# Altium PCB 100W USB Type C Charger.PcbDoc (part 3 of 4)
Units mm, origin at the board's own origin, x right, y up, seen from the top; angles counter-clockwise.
Board outline 79.45 x 55.68 mm, 4 copper layers (Top Layer, Signal Layer 1, Signal Layer 2, Bottom Layer), stack 1.565 mm thick; 161 components, 84 nets, 462 pads, 2175 vias.
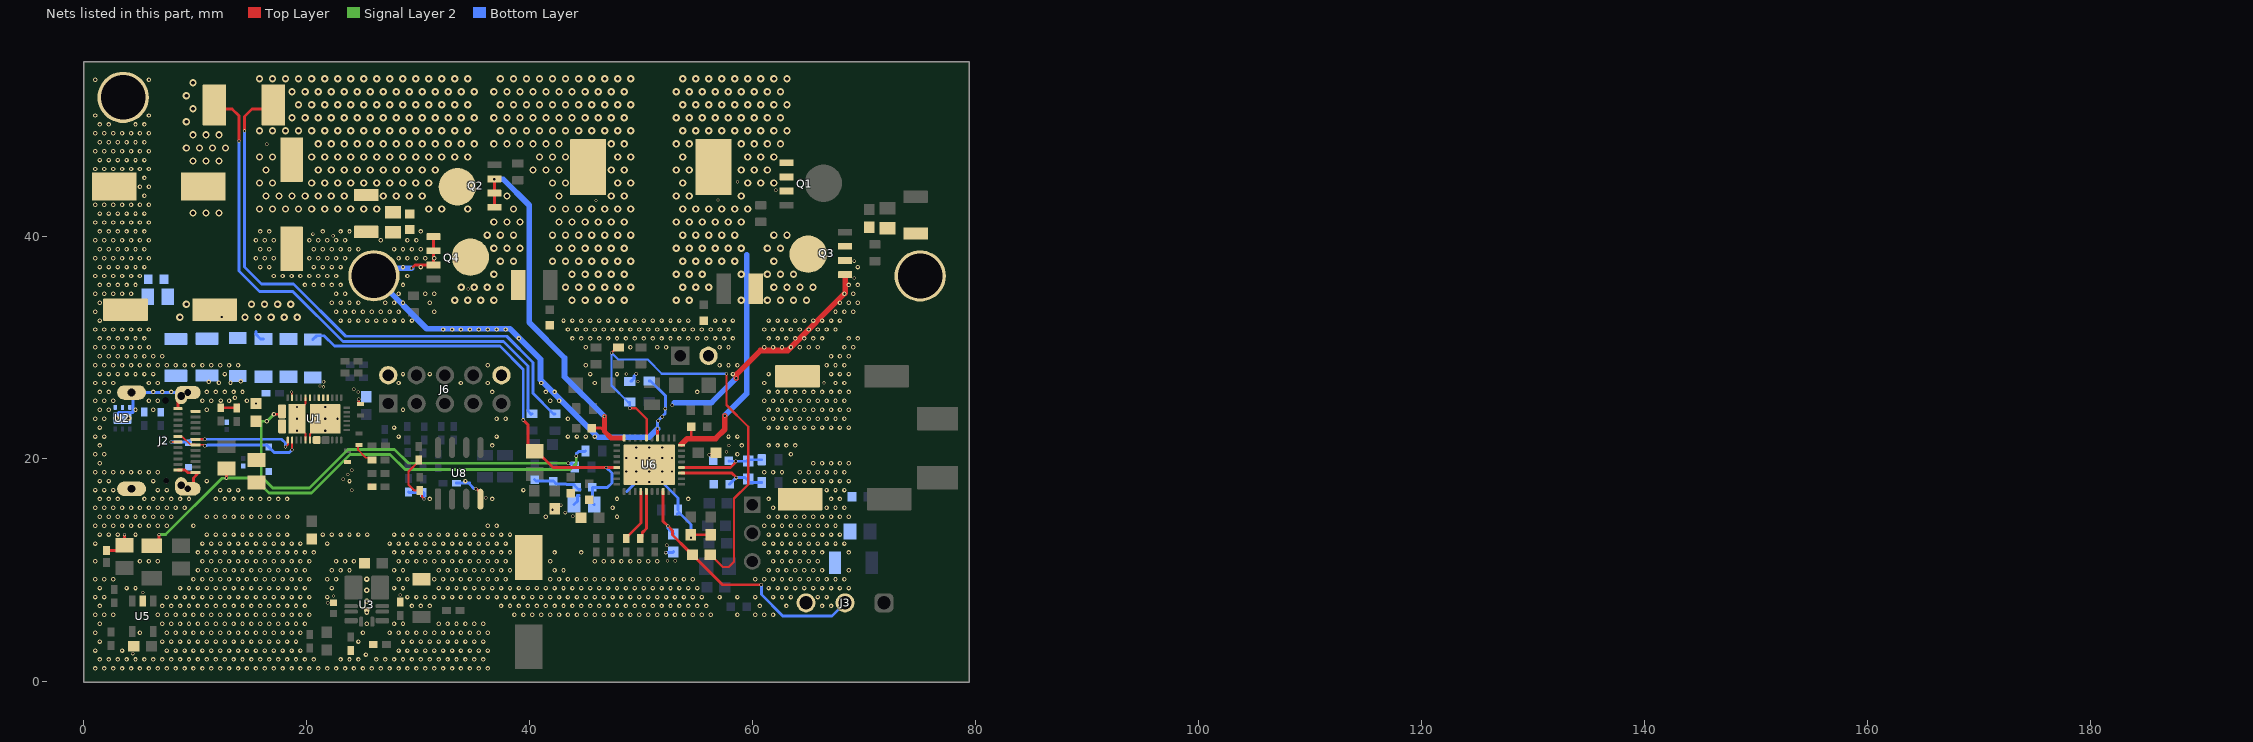
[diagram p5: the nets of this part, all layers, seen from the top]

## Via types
v1: diameter 0.4, hole 0.2, Top Layer to Bottom Layer, 1357 vias
v2: diameter 0.66, hole 0.33, Top Layer to Bottom Layer, 627 vias
v3: diameter 0.3, hole 0.2, Top Layer to Bottom Layer, tented both sides, 152 vias
v4: diameter 0.5, hole 0.2, Top Layer to Bottom Layer, 18 vias
v5: diameter 0.5, hole 0.2, Top Layer to Bottom Layer, tented both sides, 16 vias
v6: diameter 0.4, hole 0.2, Top Layer to Bottom Layer, tented both sides, 3 vias
v7: diameter 0.35, hole 0.2, Top Layer to Bottom Layer, tented both sides, 2 vias

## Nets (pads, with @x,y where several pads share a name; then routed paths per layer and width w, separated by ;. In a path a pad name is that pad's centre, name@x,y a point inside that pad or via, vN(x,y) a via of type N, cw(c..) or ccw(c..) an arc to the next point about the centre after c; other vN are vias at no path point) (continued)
PGND: C1.2 C2.2 C3.2 C4.2 C5.2 C6.2 C7.1 C8.1 C9.1 C10.2 C11.2 C12.2 C13.2 C14.2 C15.2 C16.2 C17.2 C18.2 C20.2 C21.2 C22.2 C24.2 C25.2 C29.1 C30.2 C31.2 C32.2 C33.2 C35.2 C36.2 C37.2 C40.2 C41.2 C42.2 C43.1 C44.1 C47.2 C48.2 C49.1 C51.1 C53.1 C54.2 C56.2 C57.2 C58.2 C59.1 C60.2 C61.2 C62.2 C63.2 C64.2 C67.1 C68.2 C69.2 C70.2 D1.1 D2.1 D3.2 J2.A1 J2.A12 J2.B1 J2.B12 J2.S1 J2.S2 J2.S3 J2.S4 J3.3 J4.2 J6.2 J6.10 pad.2 Q3.1 Q3.2 Q3.3 Q4.1 Q4.2 Q4.3 R2.1 R17.1 R18.1 R22.1 R23.1 R24.1 R30.1 R32.2 R52.1 R54.1 R58.2 R60.1 R61.1 R62.1 R63.1 R74.1 U1.10 U1.11 U1.12 U1.14 U1.18 U1.31 U1.39 U2.1 U2.2 U2.3 U2.7@3.474,23.658 U3.10 U5.2 U6.22 U6.37 U8.4 | length 119.3
  Top Layer w0.152: v3(18.644,26.014) 18.67,25.988 18.67,25.523 U1.18@18.694,25.499 ; U1.31@20.294,21.699 20.294,22.269 21.624,23.599 v5(21.659,23.599) ; C8.1@24.584,21.265 C8.1@24.698,21.265 24.6,21.167 24.6,20.814 25.314,20.1 25.556,20.1 R2.1@25.744,19.912
  Top Layer w0.2: v3(24.674,25.362) 24.674,25.011 C9.1@24.755,24.93 ; C15.2@29.962,20.006 C15.2@29.962,20.106 ; C15.2@30.064,19.904 30.064,19.804 29.139,18.879 29.139,17.697 29.665,17.171 30.153,17.171 R22.1@30.153,17.159 30.353,16.959 30.353,16.612 30.523,16.442 v3(30.523,16.415) ; v3(35.172,17.322) 35.191,17.303 35.25,17.303 35.587,16.966 U8.4@35.587,16.395
  Top Layer w0.254: D3.2@2.04,11.799 3.19,11.799 C24.2@3.656,12.265 v3(3.656,13.213) ; J2.B1@8.443,19.017 9.092,19.017 9.342,18.767 J2.A12@10.043,18.767 ; J2.B12@8.443,24.517 8.443,25.356 8.724,25.637 J2.S1@8.743,25.637 ; J2.S2@9.343,17.322 9.405,17.322 9.842,17.759 9.842,18.303 10.163,18.625 ; J2.A1@9.728,24.267 J2.A1@10.043,24.267 ; C5.2@12.285,24.595 13.698,24.595 C6.2@13.733,24.56 13.733,24.66 C6.2@13.906,24.833 ; R30.1@25.671,17.677 R30.1@25.844,17.504 ; v3(29.4,37.103) 29.413,37.103 29.718,37.408 Q4.3@31.377,37.408 Q4.2@31.377,38.678 Q4.1@31.377,39.948 Q4.1@31.046,39.948 ; U6.22@51.481,21.883 v3(51.481,22.706) ; R60.1@54.453,13.196 R54.1@56.237,13.196 ; v3(56.123,20.387) 56.582,20.387 R61.1@56.736,20.541
  Top Layer w0.508: v3(58.548,27.247) 58.548,27.58 60.705,29.737 63.154,29.737 68.308,34.891 Q3.1@68.308,36.539
  Top Layer w1: J2.S1@8.793,25.962 J2.S1@9.343,25.962 J2.S1@9.948,25.962
  Bottom Layer w0.254: 3.131,24.17 3.118,24.183 4.418,24.183 4.418,25.838 J2.S3@4.293,25.962 J2.S1@9.343,25.962 ; R23.1@29.139,17.047 29.204,16.982 R24.1@30.453,16.982 30.514,16.921 30.514,16.424 v3(30.523,16.415) ; R74.1@33.424,17.832 34.627,17.832 34.595,17.8 34.595,17.754 35.018,17.331 35.163,17.331 v3(35.172,17.322) ; C30.2@40.452,18.157 40.596,18.013 C31.2@42.14,18.013 42.394,17.759 43.266,17.759 43.313,17.711 43.321,17.711 43.336,17.697 43.956,17.697 C43.1@44.21,17.443 44.4,17.253 C43.1@44.544,17.253 ; C41.2@43.993,15.907 44.296,16.209 44.296,16.745 44.427,16.745 44.432,16.75 ; 48.721,17.083 v4(49.571,17.933) ; C47.2@49.089,26.974 49.118,26.974 49.372,27.228 49.372,27.438 49.571,27.637 v3(49.571,27.649) ; C42.2@50.731,26.992 50.856,26.992 52.179,25.669 v3(52.179,24.517) 52.17,24.509 52.17,24.082 51.892,23.804 v3(51.892,23.791) v3(51.535,23.434) 51.481,23.381 v3@51.481,22.718 ; v4(51.891,17.933) 53.31,16.514 R58.2@53.31,15.423 ; v3(52.214,11.601) 52.841,11.601 R62.1@52.905,11.665 R62.1@52.905,11.69 ; R58.2@53.253,15.05 53.401,15.198 53.41,15.198 54.491,14.117 v3(54.491,12.934)
  Bottom Layer w0.5: 46.14,21.95 46.149,21.959 48.629,21.959 48.638,21.95 50.726,21.95
  Bottom Layer w0.508: v3(29.4,37.103) 27.719,37.103 26.537,35.921 30.77,31.688 38.237,31.688 40.979,28.946 40.979,27.111 46.14,21.95 ; 50.726,21.95 v3(51.481,22.706) ; 52.979,25.053 56.326,25.053 58.52,27.247 v3(58.548,27.247)
  other v1: 1.043,1.215 1.843,1.215 2.643,1.215 3.443,1.215 4.243,1.215 5.043,1.215 5.843,1.215 6.643,1.215 7.443,1.215 8.243,1.215 9.043,1.215 9.843,1.215 10.643,1.215 11.443,1.215 12.243,1.215 13.043,1.215 13.843,1.215 14.643,1.215 15.443,1.215 16.243,1.215 17.043,1.215 17.843,1.215 18.643,1.215 19.443,1.215 20.243,1.215 21.043,1.215 21.843,1.215 22.643,1.215 23.443,1.215 24.243,1.215 25.043,1.215 25.843,1.215 26.643,1.215 27.443,1.215 28.243,1.215 29.043,1.215 29.843,1.215 30.643,1.215 31.443,1.215 32.243,1.215 33.043,1.215 33.843,1.215 34.643,1.215 35.443,1.215 36.243,1.215 1.443,2.015 2.243,2.015 3.043,2.015 3.843,2.015 4.643,2.015 5.443,2.015 6.243,2.015 7.043,2.015 7.843,2.015 8.643,2.015 9.443,2.015 10.243,2.015 11.043,2.015 11.843,2.015 12.643,2.015 13.443,2.015 14.243,2.015 15.043,2.015 15.843,2.015 16.643,2.015 17.443,2.015 18.243,2.015 19.043,2.015 19.843,2.015 20.643,2.015 23.043,2.015 23.843,2.015 24.643,2.015 26.243,2.015 27.043,2.015 27.843,2.015 28.643,2.015 29.443,2.015 30.243,2.015 31.043,2.015 31.843,2.015 32.643,2.015 33.443,2.015 34.243,2.015 35.043,2.015 35.843,2.015 1.043,2.815 3.443,2.815 7.443,2.815 8.243,2.815 9.043,2.815 9.843,2.815 10.643,2.815 11.443,2.815 12.243,2.815 13.043,2.815 13.843,2.815 14.643,2.815 15.443,2.815 16.243,2.815 17.043,2.815 17.843,2.815 18.643,2.815 19.443,2.815 28.243,2.815 29.043,2.815 29.843,2.815 30.643,2.815 31.443,2.815 32.243,2.815 33.043,2.815 33.843,2.815 34.643,2.815 35.443,2.815 36.243,2.815 1.443,3.615 7.043,3.615 7.843,3.615 8.643,3.615 9.443,3.615 10.243,3.615 11.043,3.615 11.843,3.615 12.643,3.615 13.443,3.615 14.243,3.615 15.043,3.615 15.843,3.615 16.643,3.615 17.443,3.615 18.243,3.615 19.043,3.615 24.643,3.615 28.643,3.615 29.443,3.615 30.243,3.615 31.043,3.615 31.843,3.615 32.643,3.615 33.443,3.615 34.243,3.615 35.043,3.615 35.843,3.615 1.043,4.415 5.043,4.415 7.443,4.415 8.243,4.415 9.043,4.415 9.843,4.415 10.643,4.415 11.443,4.415 12.243,4.415 13.043,4.415 13.843,4.415 14.643,4.415 15.443,4.415 16.243,4.415 17.043,4.415 17.843,4.415 18.643,4.415 19.443,4.415 25.043,4.415 27.443,4.415 28.243,4.415 29.043,4.415 29.843,4.415 30.643,4.415 31.443,4.415 32.243,4.415 33.043,4.415 33.843,4.415 34.643,4.415 35.443,4.415 36.243,4.415 1.443,5.215 7.043,5.215 7.843,5.215 8.643,5.215 9.443,5.215 10.243,5.215 11.043,5.215 11.843,5.215 12.643,5.215 13.443,5.215 14.243,5.215 15.043,5.215 15.843,5.215 16.643,5.215 17.443,5.215 18.243,5.215 19.043,5.215 19.843,5.215 27.843,5.215 28.643,5.215 31.843,5.215 32.643,5.215 33.443,5.215 34.243,5.215 35.043,5.215 35.843,5.215 1.043,6.015 1.843,6.015 2.643,6.015 6.643,6.015 7.443,6.015 8.243,6.015 9.043,6.015 9.843,6.015 10.643,6.015 11.443,6.015 12.243,6.015 13.043,6.015 13.843,6.015 14.643,6.015 15.443,6.015 16.243,6.015 17.043,6.015 17.843,6.015 18.643,6.015 19.443,6.015 20.243,6.015 38.643,6.015 39.443,6.015 40.243,6.015 41.043,6.015 41.843,6.015 42.643,6.015 43.443,6.015 44.243,6.015 45.043,6.015 45.843,6.015 46.643,6.015 47.443,6.015 48.243,6.015 49.043,6.015 49.843,6.015 50.643,6.015 51.443,6.015 52.243,6.015 53.043,6.015 53.843,6.015 54.643,6.015 55.443,6.015 56.243,6.015 58.643,6.015 60.243,6.015 61.043,6.015 61.843,6.015 1.443,6.815 7.043,6.815 7.843,6.815 8.643,6.815 9.443,6.815 10.243,6.815 11.043,6.815 11.843,6.815 12.643,6.815 13.443,6.815 14.243,6.815 15.043,6.815 15.843,6.815 16.643,6.815 17.443,6.815 18.243,6.815 19.043,6.815 19.843,6.815 29.443,6.815 30.243,6.815 31.043,6.815 37.443,6.815 38.243,6.815 39.043,6.815 39.843,6.815 40.643,6.815 41.443,6.815 42.243,6.815 43.043,6.815 43.843,6.815 44.643,6.815 45.443,6.815 46.243,6.815 47.043,6.815 47.843,6.815 48.643,6.815 49.443,6.815 50.243,6.815 51.043,6.815 51.843,6.815 52.643,6.815 53.443,6.815 54.243,6.815 55.043,6.815 55.843,6.815 60.643,6.815 63.043,6.815 66.243,6.815 67.043,6.815 1.043,7.615 1.843,7.615 7.443,7.615 8.243,7.615 9.043,7.615 9.843,7.615 10.643,7.615 11.443,7.615 12.243,7.615 13.043,7.615 13.843,7.615 14.643,7.615 15.443,7.615 16.243,7.615 17.043,7.615 17.843,7.615 18.643,7.615 19.443,7.615 20.243,7.615 21.843,7.615 29.043,7.615 29.843,7.615 30.643,7.615 31.443,7.615 32.243,7.615 33.043,7.615 33.843,7.615 34.643,7.615 35.443,7.615 36.243,7.615 37.043,7.615 37.843,7.615 38.643,7.615 39.443,7.615 40.243,7.615 41.043,7.615 41.843,7.615 42.643,7.615 43.443,7.615 44.243,7.615 45.043,7.615 45.843,7.615 46.643,7.615 47.443,7.615 48.243,7.615 49.043,7.615 49.843,7.615 50.643,7.615 51.443,7.615 52.243,7.615 53.043,7.615 53.843,7.615 54.643,7.615 55.443,7.615 57.043,7.615 58.643,7.615 60.243,7.615 61.843,7.615 62.643,7.615 63.443,7.615 65.843,7.615 66.643,7.615 1.443,8.415 3.843,8.415 4.643,8.415 8.643,8.415 9.443,8.415 10.243,8.415 11.043,8.415 11.843,8.415 12.643,8.415 13.443,8.415 14.243,8.415 15.043,8.415 15.843,8.415 16.643,8.415 17.443,8.415 18.243,8.415 19.043,8.415 19.843,8.415 22.243,8.415 27.843,8.415 28.643,8.415 31.843,8.415 32.643,8.415 33.443,8.415 34.243,8.415 35.043,8.415 35.843,8.415 36.643,8.415 37.443,8.415 38.243,8.415 39.043,8.415 39.843,8.415 40.643,8.415 41.443,8.415 42.243,8.415 43.043,8.415 43.843,8.415 44.643,8.415 45.443,8.415 46.243,8.415 47.043,8.415 47.843,8.415 48.643,8.415 49.443,8.415 50.243,8.415 51.043,8.415 51.843,8.415 52.643,8.415 53.443,8.415 54.243,8.415 55.043,8.415 61.443,8.415 62.243,8.415 63.043,8.415 63.843,8.415 64.643,8.415 65.443,8.415 66.243,8.415 67.043,8.415 67.843,8.415 68.643,8.415 1.043,9.215 1.843,9.215 2.643,9.215 9.843,9.215 10.643,9.215 11.443,9.215 12.243,9.215 13.043,9.215 13.843,9.215 14.643,9.215 15.443,9.215 16.243,9.215 17.043,9.215 17.843,9.215 18.643,9.215 19.443,9.215 20.243,9.215 21.843,9.215 22.643,9.215 28.243,9.215 29.043,9.215 31.443,9.215 32.243,9.215 33.043,9.215 33.843,9.215 34.643,9.215 35.443,9.215 36.243,9.215 37.043,9.215 37.843,9.215 41.843,9.215 42.643,9.215 43.443,9.215 44.243,9.215 45.043,9.215 45.843,9.215 46.643,9.215 47.443,9.215 48.243,9.215 49.043,9.215 49.843,9.215 50.643,9.215 51.443,9.215 52.243,9.215 53.043,9.215 53.843,9.215 54.643,9.215 60.243,9.215 61.043,9.215 61.843,9.215 62.643,9.215 63.443,9.215 64.243,9.215 65.043,9.215 65.843,9.215 66.643,9.215 67.443,9.215 68.243,9.215 10.243,10.015 11.043,10.015 11.843,10.015 12.643,10.015 13.443,10.015 14.243,10.015 15.043,10.015 15.843,10.015 16.643,10.015 17.443,10.015 18.243,10.015 19.043,10.015 19.843,10.015 22.243,10.015 23.043,10.015 23.843,10.015 27.843,10.015 28.643,10.015 31.843,10.015 32.643,10.015 33.443,10.015 34.243,10.015 35.043,10.015 35.843,10.015 36.643,10.015 37.443,10.015 38.243,10.015 42.243,10.015 43.043,10.015 61.443,10.015 62.243,10.015 63.043,10.015 63.843,10.015 64.643,10.015 65.443,10.015 66.243,10.015 68.643,10.015 1.043,10.815 5.043,10.815 5.843,10.815 6.643,10.815 10.643,10.815 11.443,10.815 12.243,10.815 13.043,10.815 13.843,10.815 14.643,10.815 15.443,10.815 16.243,10.815 17.043,10.815 17.843,10.815 18.643,10.815 19.443,10.815 20.243,10.815 22.643,10.815 23.443,10.815 24.243,10.815 28.243,10.815 29.043,10.815 29.843,10.815 30.643,10.815 31.443,10.815 32.243,10.815 33.043,10.815 33.843,10.815 34.643,10.815 35.443,10.815 36.243,10.815 37.043,10.815 37.843,10.815 41.843,10.815 45.843,10.815 46.643,10.815 47.443,10.815 48.243,10.815 49.043,10.815 49.843,10.815 50.643,10.815 51.443,10.815 61.843,10.815 62.643,10.815 63.443,10.815 64.243,10.815 65.043,10.815 65.843,10.815 10.243,11.615 11.043,11.615 11.843,11.615 12.643,11.615 13.443,11.615 14.243,11.615 15.043,11.615 15.843,11.615 16.643,11.615 17.443,11.615 18.243,11.615 19.043,11.615 19.843,11.615 20.643,11.615 27.843,11.615 28.643,11.615 29.443,11.615 30.243,11.615 31.043,11.615 31.843,11.615 32.643,11.615 33.443,11.615 34.243,11.615 35.043,11.615 35.843,11.615 36.643,11.615 37.443,11.615 38.243,11.615 42.243,11.615 44.643,11.615 61.443,11.615 62.243,11.615 63.043,11.615 63.843,11.615 64.643,11.615 65.443,11.615 66.243,11.615 68.643,11.615 1.043,12.415 10.643,12.415 11.443,12.415 12.243,12.415 13.043,12.415 13.843,12.415 14.643,12.415 15.443,12.415 16.243,12.415 17.043,12.415 17.843,12.415 18.643,12.415 19.443,12.415 21.843,12.415 27.443,12.415 28.243,12.415 29.043,12.415 29.843,12.415 30.643,12.415 31.443,12.415 32.243,12.415 33.043,12.415 33.843,12.415 34.643,12.415 35.443,12.415 36.243,12.415 37.043,12.415 37.843,12.415 61.043,12.415 61.843,12.415 62.643,12.415 63.443,12.415 64.243,12.415 65.043,12.415 65.843,12.415 66.643,12.415 67.443,12.415 68.243,12.415 1.443,13.215 2.243,13.215 3.043,13.215 4.643,13.215 11.043,13.215 11.843,13.215 12.643,13.215 13.443,13.215 14.243,13.215 15.043,13.215 15.843,13.215 16.643,13.215 17.443,13.215 18.243,13.215 21.443,13.215 22.243,13.215 23.043,13.215 23.843,13.215 24.643,13.215 25.443,13.215 27.843,13.215 28.643,13.215 29.443,13.215 30.243,13.215 31.043,13.215 31.843,13.215 32.643,13.215 33.443,13.215 34.243,13.215 35.043,13.215 35.843,13.215 36.643,13.215 37.443,13.215 38.243,13.215 61.443,13.215 62.243,13.215 63.043,13.215 63.843,13.215 64.643,13.215 65.443,13.215 66.243,13.215 67.043,13.215 67.843,13.215 1.043,14.015 1.843,14.015 2.643,14.015 3.443,14.015 4.243,14.015 5.043,14.015 5.843,14.015 6.643,14.015 7.443,14.015 9.843,14.015 36.243,14.015 37.043,14.015 61.043,14.015 61.843,14.015 62.643,14.015 63.443,14.015 64.243,14.015 65.043,14.015 65.843,14.015 66.643,14.015 67.443,14.015 1.443,14.815 2.243,14.815 3.043,14.815 3.843,14.815 4.643,14.815 5.443,14.815 6.243,14.815 7.043,14.815 7.843,14.815 11.043,14.815 11.843,14.815 12.643,14.815 13.443,14.815 14.243,14.815 15.043,14.815 15.843,14.815 16.643,14.815 17.443,14.815 18.243,14.815 41.443,14.815 47.843,14.815 61.443,14.815 62.243,14.815 63.043,14.815 63.843,14.815 64.643,14.815 65.443,14.815 66.243,14.815 67.043,14.815 67.843,14.815 68.643,14.815 1.043,15.615 1.843,15.615 2.643,15.615 3.443,15.615 4.243,15.615 5.043,15.615 5.843,15.615 6.643,15.615 7.443,15.615 8.243,15.615 9.043,15.615 47.443,15.615 61.843,15.615 66.643,15.615 67.443,15.615 68.243,15.615 1.443,16.415 2.243,16.415 3.043,16.415 5.443,16.415 6.243,16.415 7.043,16.415 7.843,16.415 8.643,16.415 9.443,16.415 11.843,16.415 12.643,16.415 13.443,16.415 14.243,16.415 15.043,16.415 15.843,16.415 16.643,16.415 17.443,16.415 18.243,16.415 31.043,16.415 36.643,16.415 47.843,16.415 54.243,16.415 61.443,16.415 67.043,16.415 67.843,16.415 1.043,17.215 1.843,17.215 2.643,17.215 6.643,17.215 7.443,17.215 12.243,17.215 13.043,17.215 13.843,17.215 39.443,17.215 66.643,17.215 67.443,17.215 68.243,17.215 1.443,18.015 2.243,18.015 6.243,18.015 11.043,18.015 23.843,18.015 34.243,18.015 63.843,18.015 64.643,18.015 65.443,18.015 66.243,18.015 67.043,18.015 67.843,18.015 68.643,18.015 1.043,18.815 1.843,18.815 2.643,18.815 3.443,18.815 4.243,18.815 5.043,18.815 5.843,18.815 6.643,18.815 61.043,18.815 61.843,18.815 62.643,18.815 64.243,18.815 65.043,18.815 65.843,18.815 66.643,18.815 67.443,18.815 68.243,18.815 1.443,19.615 65.443,19.615 66.243,19.615 67.043,19.615 67.843,19.615 68.643,19.615 1.043,20.415 1.843,20.415 58.643,20.415 63.443,20.415 1.443,21.215 36.643,21.215 59.043,21.215 61.443,21.215 62.243,21.215 63.043,21.215 63.843,21.215 1.043,22.015 1.843,22.015 28.243,22.015 37.043,22.015 43.443,22.015 44.243,22.015 45.043,22.015 45.843,22.015 57.843,22.015 58.643,22.015 1.443,22.815 27.843,22.815 61.443,22.815 62.243,22.815 63.043,22.815 63.843,22.815 64.643,22.815 65.443,22.815 66.243,22.815 67.043,22.815 67.843,22.815 68.643,22.815 1.043,23.615 1.843,23.615 37.043,23.615 37.843,23.615 43.443,23.615 61.043,23.615 61.843,23.615 62.643,23.615 63.443,23.615 64.243,23.615 65.043,23.615 65.843,23.615 66.643,23.615 67.443,23.615 68.243,23.615 1.443,24.415 2.243,24.415 4.643,24.415 6.243,24.415 11.043,24.415 28.643,24.415 61.443,24.415 62.243,24.415 63.043,24.415 63.843,24.415 64.643,24.415 65.443,24.415 66.243,24.415 67.043,24.415 67.843,24.415 68.643,24.415 15.451,24.984 1.043,25.215 1.843,25.215 2.643,25.215 5.843,25.215 6.643,25.215 10.643,25.215 11.443,25.215 13.043,25.215 14.643,25.215 41.843,25.215 42.643,25.215 61.043,25.215 61.843,25.215 62.643,25.215 63.443,25.215 64.243,25.215 65.043,25.215 65.843,25.215 66.643,25.215 67.443,25.215 68.243,25.215 12.292,25.243 13.568,25.487 1.443,26.015 2.243,26.015 6.243,26.015 7.043,26.015 7.843,26.015 11.043,26.015 11.843,26.015 12.643,26.015 13.443,26.015 14.243,26.015 36.643,26.015 41.443,26.015 42.243,26.015 55.043,26.015 61.443,26.015 62.243,26.015 63.043,26.015 63.843,26.015 64.643,26.015 65.443,26.015 66.243,26.015 67.043,26.015 67.843,26.015 68.643,26.015 1.043,26.815 1.843,26.815 2.643,26.815 5.843,26.815 6.643,26.815 12.133,26.833 13.167,26.833 28.243,26.815 33.843,26.815 36.243,26.815 41.043,26.815 45.843,26.815 61.043,26.815 67.443,26.815 68.243,26.815 11.209,26.91 14.092,26.954 1.443,27.615 2.243,27.615 3.043,27.615 3.843,27.615 4.643,27.615 5.443,27.615 6.243,27.615 12.643,27.615 28.643,27.615 31.043,27.615 45.443,27.615 47.843,27.615 58.243,27.615 61.443,27.615 67.043,27.615 67.843,27.615 68.643,27.615 1.043,28.415 1.843,28.415 2.643,28.415 3.443,28.415 4.243,28.415 5.043,28.415 5.843,28.415 6.643,28.415 7.443,28.415 8.243,28.415 9.043,28.415 9.843,28.415 10.643,28.415 11.443,28.415 12.243,28.415 13.043,28.415 13.843,28.415 36.243,28.415 45.043,28.415 57.043,28.415 57.843,28.415 58.643,28.415 66.643,28.415 67.443,28.415 68.243,28.415 1.443,29.215 2.243,29.215 3.043,29.215 3.843,29.215 4.643,29.215 5.443,29.215 6.243,29.215 7.043,29.215 67.043,29.215 67.843,29.215 68.643,29.215 1.043,30.015 1.843,30.015 2.643,30.015 3.443,30.015 4.243,30.015 5.043,30.015 5.843,30.015 45.043,30.015 49.043,30.015 51.443,30.015 52.243,30.015 57.043,30.015 57.843,30.015 61.043,30.015 61.843,30.015 62.643,30.015 63.443,30.015 64.243,30.015 65.043,30.015 65.843,30.015 68.243,30.015 69.043,30.015 1.443,30.815 2.243,30.815 3.043,30.815 3.843,30.815 4.643,30.815 5.443,30.815 39.043,30.815 43.843,30.815 44.643,30.815 45.443,30.815 46.243,30.815 47.043,30.815 47.843,30.815 48.643,30.815 49.443,30.815 50.243,30.815 51.043,30.815 51.843,30.815 52.643,30.815 53.443,30.815 54.243,30.815 55.043,30.815 55.843,30.815 56.643,30.815 57.443,30.815 58.243,30.815 61.443,30.815 62.243,30.815 63.043,30.815 63.843,30.815 64.643,30.815 65.443,30.815 66.243,30.815 68.643,30.815 69.443,30.815 1.043,31.615 1.843,31.615 2.643,31.615 3.443,31.615 4.243,31.615 5.043,31.615 5.843,31.615 32.243,31.615 33.043,31.615 33.843,31.615 34.643,31.615 35.443,31.615 36.243,31.615 37.043,31.615 37.843,31.615 43.443,31.615 44.243,31.615 45.043,31.615 45.843,31.615 46.643,31.615 47.443,31.615 48.243,31.615 49.043,31.615 49.843,31.615 50.643,31.615 51.443,31.615 52.243,31.615 53.043,31.615 53.843,31.615 54.643,31.615 55.443,31.615 56.243,31.615 57.043,31.615 57.843,31.615 61.043,31.615 61.843,31.615 62.643,31.615 63.443,31.615 64.243,31.615 65.043,31.615 65.843,31.615 66.643,31.615 67.443,31.615 1.443,32.415 23.043,32.415 23.843,32.415 24.643,32.415 25.443,32.415 26.243,32.415 27.043,32.415 27.843,32.415 28.643,32.415 29.443,32.415 43.043,32.415 43.843,32.415 44.643,32.415 45.443,32.415 46.243,32.415 47.043,32.415 47.843,32.415 48.643,32.415 49.443,32.415 50.243,32.415 51.043,32.415 51.843,32.415 52.643,32.415 53.443,32.415 54.243,32.415 56.643,32.415 57.443,32.415 58.243,32.415 61.443,32.415 62.243,32.415 63.043,32.415 63.843,32.415 64.643,32.415 65.443,32.415 66.243,32.415 67.043,32.415 67.843,32.415 1.043,33.215 22.643,33.215 23.443,33.215 24.243,33.215 25.043,33.215 25.843,33.215 26.643,33.215 27.443,33.215 28.243,33.215 31.443,33.215 67.443,33.215 68.243,33.215 69.043,33.215 1.443,34.015 22.243,34.015 23.043,34.015 23.843,34.015 24.643,34.015 27.043,34.015 27.843,34.015 28.643,34.015 31.043,34.015 67.843,34.015 68.643,34.015 69.443,34.015 1.043,34.815 1.843,34.815 2.643,34.815 3.443,34.815 4.243,34.815 22.643,34.815 23.443,34.815 28.243,34.815 30.643,34.815 31.443,34.815 68.243,34.815 69.043,34.815 1.443,35.615 2.243,35.615 3.043,35.615 3.843,35.615 4.643,35.615 19.843,35.615 20.643,35.615 21.443,35.615 22.243,35.615 23.043,35.615 28.643,35.615 68.643,35.615 69.443,35.615 1.043,36.415 1.843,36.415 2.643,36.415 3.443,36.415 4.243,36.415 5.043,36.415 17.043,36.415 17.843,36.415 18.643,36.415 19.443,36.415 20.243,36.415 21.043,36.415 21.843,36.415 22.643,36.415 29.043,36.415 1.443,37.215 2.243,37.215 3.043,37.215 3.843,37.215 4.643,37.215 5.443,37.215 15.843,37.215 16.643,37.215 20.643,37.215 21.443,37.215 22.243,37.215 23.043,37.215 28.643,37.215 30.243,37.215 69.443,37.215 1.043,38.015 1.843,38.015 2.643,38.015 3.443,38.015 4.243,38.015 5.043,38.015 5.843,38.015 15.443,38.015 16.243,38.015 17.043,38.015 20.243,38.015 21.043,38.015 21.843,38.015 22.643,38.015 23.443,38.015 28.243,38.015 29.043,38.015 29.843,38.015 30.643,38.015 31.443,38.015 1.443,38.815 2.243,38.815 3.043,38.815 3.843,38.815 4.643,38.815 5.443,38.815 15.843,38.815 16.643,38.815 20.643,38.815 21.443,38.815 22.243,38.815 23.043,38.815 23.843,38.815 24.643,38.815 27.843,38.815 28.643,38.815 29.443,38.815 30.243,38.815 1.043,39.615 1.843,39.615 2.643,39.615 3.443,39.615 4.243,39.615 5.043,39.615 5.843,39.615 15.443,39.615 16.243,39.615 17.043,39.615 20.243,39.615 21.043,39.615 21.843,39.615 22.643,39.615 23.443,39.615 26.643,39.615 29.043,39.615 29.843,39.615 1.443,40.415 2.243,40.415 3.043,40.415 3.843,40.415 4.643,40.415 5.443,40.415 15.843,40.415 16.643,40.415 21.443,40.415 23.043,40.415 23.843,40.415 30.243,40.415 1.043,41.215 1.843,41.215 2.643,41.215 3.443,41.215 4.243,41.215 5.043,41.215 5.843,41.215 1.443,42.015 2.243,42.015 3.043,42.015 3.843,42.015 4.643,42.015 5.443,42.015 1.043,42.815 1.843,42.815 2.643,42.815 3.443,42.815 4.243,42.815 5.043,42.815 5.843,42.815 5.443,43.615 5.043,44.415 5.843,44.415 5.443,45.215 1.043,46.015 1.843,46.015 2.643,46.015 3.443,46.015 4.243,46.015 5.043,46.015 5.843,46.015 1.443,46.815 2.243,46.815 3.043,46.815 3.843,46.815 4.643,46.815 5.443,46.815 1.043,47.615 1.843,47.615 2.643,47.615 3.443,47.615 4.243,47.615 5.043,47.615 5.843,47.615 1.443,48.415 2.243,48.415 3.043,48.415 3.843,48.415 4.643,48.415 5.443,48.415 1.043,49.215 1.843,49.215 2.643,49.215 3.443,49.215 4.243,49.215 5.043,49.215 5.843,49.215 1.443,50.015 2.243,50.015 4.643,50.015 5.443,50.015 1.043,50.815 5.843,50.815 1.043,54.015 5.843,54.015
  other v3: 4.405,2.541 21.894,7.098 22.404,7.713 28.387,7.795 5.291,8.025 52.373,10.876 53.069,10.876 52.297,12.267 43.87,14.859 43.208,15.19 42.051,15.451 42.822,15.859 36.075,16.514 24.039,17.2 23.28,18.182 23.683,18.601 24.042,18.989 57.663,20.653 57.875,21.216 52.806,24.82 24.623,26.003 24.216,26.255 21.505,26.467 21.191,26.55 66.41,26.825 21.522,26.935 49.704,26.954 48.684,27.621 69.133,36.234 69.133,37.749 22.37,40.022 20.56,40.173
  other v4: 50.731,17.933 48.681,18.868 49.571,18.868 50.731,18.868 51.891,18.868 52.781,18.868 48.681,20.098 49.571,20.098 50.731,20.098 51.891,20.098 52.781,20.098 49.571,21.033 50.731,21.033 51.891,21.033 2.924,23.658 4.024,23.658
  other v5: 25.39,7.222 25.39,8.222 25.39,9.222 21.659,22.524 20.549,23.599 22.769,23.599 21.659,24.674
  other v6: 25.314,2.451 25.39,5.222 25.39,6.222
PPHV: C12.1 C13.1 C14.1 C20.1 C29.2 C41.1 C43.2 C44.2 C48.1 C57.1 C58.1 C60.1 C70.1 R31.1 R33.2 R46.2 R56.1 U1.20 U1.21 U1.22 U6.33 | length 130.5
  Top Layer w0.254: R31.1@11.729,51.771 12.098,51.402 13.317,51.402 13.929,50.79 v3(13.929,48.529) ; v1(17.062,24.017) 17.582,24.017 17.805,24.24 U1.20@17.805,24.306 ; v3(39.428,23.504) 39.863,23.069 39.863,21.201 40.371,20.693 40.635,20.693 42.095,19.233 v3(46.884,19.233) U6.33@47.658,19.233
  Signal Layer 2 w0.254: v1(17.062,24.017) v1(16.428,23.383) 15.926,23.383 15.926,18.424 16.96,17.39 20.239,17.39 23.707,20.858 27.891,20.858 29.137,19.612 v3(43.462,19.612)
  Bottom Layer w0.254: v3(13.929,48.529) 13.925,48.525 13.925,36.871 15.761,35.036 18.755,35.036 23.264,30.527 37.656,30.527 39.844,28.339 39.844,24.309 R33.2@40.092,24.061 ; 15.446,31.442 15.446,31.192 15.869,30.769 C20.1@16.119,30.769 ; C13.1@20.552,30.708 20.905,31.061 21.57,31.061 22.504,30.126 37.338,30.126 39.428,28.037 v3(39.428,23.504) ; R33.2@40.136,23.99 R33.2@40.207,24.061 ; v3(43.462,19.612) 43.47,19.604 43.805,19.604 44.053,19.356 R56.1@44.053,19.272 ; C41.1@45.793,15.907 45.633,16.067 C43.2@45.633,17.443 46.967,17.443 47.379,17.854 47.379,18.738 v3(46.884,19.233)
  other v2: 8.629,32.716 14.471,32.716 15.639,32.716 16.807,32.716 17.976,32.716 19.144,32.716 9.213,33.884 15.055,33.884 16.223,33.884 17.392,33.884 18.56,33.884 9.797,42.063 10.965,42.063 12.134,42.063 9.797,46.737 10.965,46.737 12.134,46.737 9.213,47.905 10.381,47.905 11.55,47.905 12.718,47.905 9.797,49.074 10.965,49.074 12.134,49.074 9.213,50.242 9.797,51.41 9.213,52.579 9.797,53.747
  other v3: 12.38,32.73
REGN: C47.1 R55.1 R57.2 U6.24 | length 42.2
  Top Layer w0.2: v3(47.354,29.523) 47.838,30.007 R55.1@47.963,30.007 ; v3(48.981,24.549) 49.551,24.549 50.506,23.594 50.506,21.908 U6.24@50.481,21.883 ; R57.2@56.211,11.397 56.236,11.397 57.329,10.304 57.875,10.304 58.348,10.778 58.348,16.445 59.614,17.711 59.614,22.892 57.662,24.844 v3(57.662,27.649)
  Bottom Layer w0.2: v3(48.981,24.549) 48.981,25.099 48.856,25.099 47.354,26.601 v3(47.354,29.523) 47.954,28.923 50.591,28.923 51.865,27.649 v3(57.662,27.649)
SRN: C28.2 C33.1 R37.2 U6.13 | length 8.4
  Top Layer w0.254: U6.13@53.631,18.733 58.141,18.733 v3(58.548,18.327)
  Bottom Layer w0.254: C33.1@57.938,17.727 58.538,18.327 59.34,18.327 59.767,17.899 R37.2@60.833,17.899
SRP: C28.1 C32.1 R36.2 U6.14 | length 8.2
  Top Layer w0.254: U6.14@53.631,19.233 58.033,19.233 58.481,19.681 58.481,19.783 v3(58.49,19.792)
  Bottom Layer w0.254: C32.1@57.88,19.82 57.909,19.792 59.475,19.792 59.615,19.931 R36.2@60.833,19.931
STAT1: R70.1 U6.4 | length 4.8
  Top Layer w0.254: R70.1@48.681,12.867 48.681,12.967 49.981,14.267 U6.4@49.981,17.083
STAT2: R71.1 U6.5 | length 4.4
  Top Layer w0.254: R71.1@49.931,12.867 50.104,13.04 50.104,13.387 50.481,13.764 U6.5@50.481,17.083
SW1: C38.1 L3.1 Q2.1 Q2.2 Q2.3 Q4.5-6-7-8 R42.2 U6.28 | length 33
  Top Layer w0.254: Q2.1@36.838,42.587 Q2.2@36.838,43.857 v3(36.838,45.103) ; C38.1@45.588,22.776 46.412,22.776 46.711,22.477 ; 48.341,21.883 U6.28@48.481,21.883
  Top Layer w0.43: v3(46.711,23.805) 46.711,22.477 47.305,21.883 48.341,21.883
  Bottom Layer w0.508: v3(36.838,45.103) 37.625,45.103 39.968,42.76 39.968,42.423 39.968,40.086 39.968,37.749 39.968,32.24 43.135,29.073 43.135,27.38 v3(46.711,23.805)
  other v2: 33.294,34.244 34.463,34.244 35.631,34.244 36.8,34.244 43.81,34.244 44.978,34.244 46.147,34.244 47.315,34.244 48.484,34.244 33.879,35.413 35.047,35.413 36.215,35.413 37.384,35.413 43.226,35.413 44.394,35.413 45.563,35.413 46.731,35.413 47.899,35.413 49.068,35.413 36.8,36.581 43.81,36.581 44.978,36.581 46.147,36.581 47.315,36.581 48.484,36.581 37.384,37.749 38.552,37.749 42.057,37.749 43.226,37.749 44.394,37.749 45.563,37.749 46.731,37.749 47.899,37.749 49.068,37.749 36.8,38.918 37.968,38.918 39.136,38.918 42.642,38.918 43.81,38.918 44.978,38.918 46.147,38.918 47.315,38.918 48.484,38.918 36.215,40.086 37.384,40.086 38.552,40.086 42.057,40.086 43.226,40.086 44.394,40.086 45.563,40.086 46.731,40.086 47.899,40.086 49.068,40.086 36.8,41.255 37.968,41.255 39.136,41.255 42.642,41.255 43.81,41.255 44.978,41.255 46.147,41.255 47.315,41.255 48.484,41.255 38.552,42.423 42.057,42.423 43.226,42.423 44.394,42.423 45.563,42.423 46.731,42.423 47.899,42.423 49.068,42.423 37.968,43.591 42.642,43.591 47.315,43.591 48.484,43.591 42.057,44.76 43.226,44.76 47.899,44.76 49.068,44.76 40.305,45.928 41.473,45.928 42.642,45.928 47.315,45.928 48.484,45.928 40.889,47.097 42.057,47.097 43.226,47.097 47.899,47.097 49.068,47.097 36.8,48.265 37.968,48.265 39.136,48.265 40.305,48.265 41.473,48.265 42.642,48.265 47.315,48.265 48.484,48.265 37.384,49.433 38.552,49.433 39.721,49.433 40.889,49.433 42.057,49.433 43.226,49.433 44.394,49.433 45.563,49.433 46.731,49.433 47.899,49.433 49.068,49.433 36.8,50.602 37.968,50.602 39.136,50.602 40.305,50.602 41.473,50.602 42.642,50.602 43.81,50.602 44.978,50.602 46.147,50.602 47.315,50.602 48.484,50.602 37.384,51.77 38.552,51.77 39.721,51.77 40.889,51.77 42.057,51.77 43.226,51.77 44.394,51.77 45.563,51.77 46.731,51.77 47.899,51.77 49.068,51.77 36.8,52.939 37.968,52.939 39.136,52.939 40.305,52.939 41.473,52.939 42.642,52.939 43.81,52.939 44.978,52.939 46.147,52.939 47.315,52.939 48.484,52.939 37.384,54.107 38.552,54.107 39.721,54.107 40.889,54.107 42.057,54.107 43.226,54.107 44.394,54.107 45.563,54.107 46.731,54.107 47.899,54.107 49.068,54.107
  other v3: 34.494,35.248 45.961,43.191
SW2: C39.2 L3.2 Q1.1 Q1.2 Q1.3 Q3.5-6-7-8 R43.2 U6.18 | length 22
  Top Layer w0.254: 54.392,21.823 54.507,21.938 C39.2@54.507,22.886
  Top Layer w0.508: U6.18@53.631,21.316 54.138,21.823 54.392,21.823 56.688,21.823 57.506,22.641 v3(57.506,23.887)
  Bottom Layer w0.508: v3(57.506,23.887) 59.475,25.856 59.475,38.319
  other v2: 53.157,34.244 54.326,34.244 58.999,34.244 61.336,34.244 62.504,34.244 63.673,34.244 64.841,34.244 53.741,35.413 54.91,35.413 56.078,35.413 61.92,35.413 63.089,35.413 64.257,35.413 65.425,35.413 53.157,36.581 54.326,36.581 55.494,36.581 58.999,36.581 61.336,36.581 62.504,36.581 63.673,36.581 53.741,37.749 54.91,37.749 56.078,37.749 57.247,37.749 58.415,37.749 61.92,37.749 53.157,38.918 54.326,38.918 55.494,38.918 56.662,38.918 57.831,38.918 58.999,38.918 61.336,38.918 62.504,38.918 53.741,40.086 54.91,40.086 56.078,40.086 57.247,40.086 58.415,40.086 61.92,40.086 63.089,40.086 53.157,41.255 54.326,41.255 55.494,41.255 56.662,41.255 57.831,41.255 58.999,41.255 53.741,42.423 54.91,42.423 56.078,42.423 57.247,42.423 58.415,42.423 59.583,42.423 53.157,43.591 54.326,43.591 58.999,43.591 53.741,44.76 59.583,44.76 60.752,44.76 61.92,44.76 53.157,45.928 54.326,45.928 58.999,45.928 60.168,45.928 61.336,45.928 53.741,47.097 59.583,47.097 60.752,47.097 61.92,47.097 53.157,48.265 54.326,48.265 58.999,48.265 60.168,48.265 61.336,48.265 62.504,48.265 53.741,49.433 54.91,49.433 56.078,49.433 57.247,49.433 58.415,49.433 59.583,49.433 60.752,49.433 61.92,49.433 63.089,49.433 53.157,50.602 54.326,50.602 55.494,50.602 56.662,50.602 57.831,50.602 58.999,50.602 60.168,50.602 61.336,50.602 62.504,50.602 53.741,51.77 54.91,51.77 56.078,51.77 57.247,51.77 58.415,51.77 59.583,51.77 60.752,51.77 61.92,51.77 63.089,51.77 53.157,52.939 54.326,52.939 55.494,52.939 56.662,52.939 57.831,52.939 58.999,52.939 60.168,52.939 61.336,52.939 62.504,52.939 53.741,54.107 54.91,54.107 56.078,54.107 57.247,54.107 58.415,54.107 59.583,54.107 60.752,54.107 61.92,54.107 63.089,54.107
  other v3: 56.904,43.23 62.077,44.106 58.649,44.877
TS: J3.2 R57.1 R62.2 U6.8 | length 25.2
  Top Layer w0.254: U6.8@51.981,17.083 51.981,14.413 v3(52.406,13.988) 52.833,13.561 52.833,13.175 54.238,11.77 54.238,11.745 54.402,11.581 54.427,11.581 R57.1@54.611,11.397 ; R57.1@54.414,11.568 54.414,11.13 54.903,11.13 57.323,8.71 v3(60.791,8.71)
  Bottom Layer w0.254: v3(52.406,13.988) 52.415,13.979 52.415,13.779 52.905,13.29 R62.2@52.905,13.265 ; v3(60.791,8.71) 60.791,7.832 62.708,5.915 67.122,5.915 J3.2@68.299,7.092
USB_N: D2.2 J2.A7 J2.B7 U1.27 | length 11.9
  Top Layer w0.152: J2.B7@8.443,22.017 8.502,21.959 8.899,21.959 9.531,21.326 9.985,21.326 J2.A7@10.043,21.267 10.739,21.267 10.812,21.194 v3(10.852,21.194) ; v3(18.689,20.82) 18.692,20.823 18.692,21.697 U1.27@18.694,21.699
  Bottom Layer w0.254: v3(10.852,21.194) 10.861,21.203 11.039,21.203 11.095,21.259 11.49,21.259 11.495,21.254 16.415,21.254 17.097,20.573 18.442,20.573 v3(18.689,20.82)
USB_P: D1.2 J2.A6 J2.B6 U1.26 | length 13.1
  Top Layer w0.152: v3(7.832,21.517) J2.B6@8.443,21.517 ; J2.A6@10.043,21.767 J2.A6@10.046,21.77 ; v3(18.105,21.087) 18.14,21.087 18.318,21.265 18.318,21.475 U1.26@18.294,21.499
  Top Layer w0.2: J2.A6@10.043,21.767 10.045,21.766 v3(10.852,21.764) v3(10.852,21.764) ; v3(18.105,21.087) v3@18.124,21.106 ; U1.26@18.294,21.499 U1.26@18.294,21.699
  Bottom Layer w0.152: D1.2@9.329,21.539 D1.2@9.399,21.468
  Bottom Layer w0.254: v3(7.832,21.517) 7.841,21.509 9.298,21.509 D1.2@9.329,21.539 ; D1.2@9.399,21.468 9.695,21.764 17.755,21.764 18.096,21.423 18.096,21.096 v3(18.105,21.087)
VBUS: C2.1 L1.2 R59.1 R75.2 U1.23 U1.24 U1.25 U1.32 U1.33 | length 46.4
  Top Layer w0.254: R75.2@6.091,12.215 6.223,12.215 6.746,12.738 v3(6.746,13.213) ; v3(12.799,18.283) L1.2@12.799,19.146
  Signal Layer 2 w0.254: v3(6.746,13.213) 7.351,13.213 12.411,18.274 12.79,18.274 v3(12.799,18.283) 15.285,18.283 16.632,16.936 20.427,16.936 23.896,20.404 27.48,20.404 28.842,19.042 43.656,19.042 44.183,19.57 v3(44.183,20.256)
  Bottom Layer w0.254: v3(44.183,20.256) 44.192,20.265 44.192,20.463 44.405,20.676 44.968,20.676 R59.1@45.017,20.725
Vdrain: U1.15 U1.30 U1.40 | length 4.9
  Top Layer w0.152: v5(19.134,22.524) U1.40@19.649,22.524 ; U1.30@19.894,21.699 19.894,22.279 U1.40@19.649,22.524 ; U1.15@19.894,25.499 19.894,24.957 19.875,24.938 19.875,24.9 19.134,24.159 v5(19.134,23.599) 19.134,23.039 U1.40@19.649,22.524
  other v5: 19.134,24.674
VSYS: C49.2 C59.2 C63.1 C64.1 Q2.5-6-7-8 R31.2 R34.2 | length 51.8
  Top Layer w0.254: v3(14.42,49.433) 14.42,50.735 15.087,51.402 16.65,51.402 R31.2@17.019,51.771 ; R31.2@16.353,50.602 R31.2@16.428,50.527
  Top Layer w2.54: Q2.5-6-7-8@33.304,44.423 Q2.5-6-7-8@33.525,44.423
  Bottom Layer w0.254: v3(14.42,49.433) 14.42,37.223 15.953,35.69 18.827,35.69 23.51,31.007 37.955,31.007 40.298,28.664 40.298,26.829 40.305,26.822 40.305,25.9 42.157,24.048 R34.2@42.282,24.048
  other v2: 15.768,42.423 16.937,42.423 18.105,42.423 19.274,42.423 20.442,42.423 21.61,42.423 22.779,42.423 23.947,42.423 25.116,42.423 26.284,42.423 30.958,42.423 32.126,42.423 34.463,42.423 16.353,43.591 17.521,43.591 18.689,43.591 19.858,43.591 21.026,43.591 22.195,43.591 23.363,43.591 26.868,43.591 28.037,43.591 29.205,43.591 30.373,43.591 15.768,44.76 16.937,44.76 20.442,44.76 21.61,44.76 22.779,44.76 23.947,44.76 25.116,44.76 26.284,44.76 27.452,44.76 28.621,44.76 29.789,44.76 30.958,44.76 16.353,45.928 21.026,45.928 22.195,45.928 23.363,45.928 24.531,45.928 25.7,45.928 26.868,45.928 28.037,45.928 29.205,45.928 30.373,45.928 31.542,45.928 15.768,47.097 16.937,47.097 20.442,47.097 21.61,47.097 22.779,47.097 23.947,47.097 25.116,47.097 26.284,47.097 27.452,47.097 28.621,47.097 29.789,47.097 30.958,47.097 32.126,47.097 33.294,47.097 34.463,47.097 21.026,48.265 22.195,48.265 23.363,48.265 24.531,48.265 25.7,48.265 26.868,48.265 28.037,48.265 29.205,48.265 30.373,48.265 31.542,48.265 32.71,48.265 33.879,48.265 35.047,48.265 15.768,49.433 16.937,49.433 18.105,49.433 19.274,49.433 20.442,49.433 21.61,49.433 22.779,49.433 23.947,49.433 25.116,49.433 26.284,49.433 27.452,49.433 28.621,49.433 29.789,49.433 30.958,49.433 32.126,49.433 33.294,49.433 34.463,49.433 18.689,50.602 19.858,50.602 21.026,50.602 22.195,50.602 23.363,50.602 24.531,50.602 25.7,50.602 26.868,50.602 28.037,50.602 29.205,50.602 30.373,50.602 31.542,50.602 32.71,50.602 33.879,50.602 35.047,50.602 19.274,51.77 20.442,51.77 21.61,51.77 22.779,51.77 23.947,51.77 25.116,51.77 26.284,51.77 27.452,51.77 28.621,51.77 29.789,51.77 30.958,51.77 32.126,51.77 33.294,51.77 34.463,51.77 18.689,52.939 19.858,52.939 21.026,52.939 22.195,52.939 23.363,52.939 24.531,52.939 25.7,52.939 26.868,52.939 28.037,52.939 29.205,52.939 30.373,52.939 31.542,52.939 32.71,52.939 33.879,52.939 35.047,52.939 15.768,54.107 16.937,54.107 18.105,54.107 19.274,54.107 20.442,54.107 21.61,54.107 22.779,54.107 23.947,54.107 25.116,54.107 26.284,54.107 27.452,54.107 28.621,54.107 29.789,54.107 30.958,54.107 32.126,54.107 33.294,54.107 34.463,54.107
  other v3: 16.428,48.24
pads on no net: J2.A2 J2.A3 J2.A8 J2.A10 J2.A11 J2.ALIGN1 J2.ALIGN2 J2.B2 J2.B3 J2.B8 J2.B10 J2.B11 J6.4 J6.5 J6.7 J6.9 LBL1.0 U2.7@3.024,23.658 U2.7@3.924,23.658 U3.1 U3.7 U5.4 U6.15 U6.16 U6.31
copper on no net: | length 1351.8
  Top Layer w0.381: 103.52,11.527 113.932,11.527 137.801,11.527 159.64,11.527 176.145,11.527 190.62,11.527 ; 103.52,14.575 113.932,14.575 137.801,14.575 159.64,14.575 176.145,14.575 190.62,14.575 ; 103.52,17.623 113.932,17.623 137.801,17.623 159.64,17.623 176.145,17.623 190.62,17.623 ; 103.52,20.671 113.932,20.671 137.801,20.671 159.64,20.671 176.145,20.671 190.62,20.671 ; 103.52,23.719 113.932,23.719 137.801,23.719 159.64,23.719 176.145,23.719 190.62,23.719 ; 103.52,26.767 113.932,26.767 137.801,26.767 159.64,26.767 176.145,26.767 190.62,26.767 ; 103.52,29.815 113.932,29.815 137.801,29.815 159.64,29.815 176.145,29.815 190.62,29.815 ; 103.52,32.863 113.932,32.863 137.801,32.863 159.64,32.863 176.145,32.863 190.62,32.863 ; 103.52,35.911 113.932,35.911 137.801,35.911 159.64,35.911 176.145,35.911 190.62,35.911 ; 103.52,38.959 113.932,38.959 137.801,38.959 159.64,38.959 176.145,38.959 190.62,38.959 ; 103.52,42.007 190.62,42.007 ; 113.932,45.055 113.932,8.479 ; 137.801,45.055 137.801,8.479 ; 159.64,45.055 159.64,8.479 ; 176.145,45.055 176.145,8.479 ; 113.932,8.479 103.52,8.479 103.52,45.055 190.62,45.055 190.62,8.479 176.145,8.479 ; 113.932,8.479 137.801,8.479 ; 137.801,8.479 159.64,8.479 ; 159.64,8.479 176.145,8.479

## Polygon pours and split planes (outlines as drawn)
PGND on Top Layer "TOP_LAYER_PGND_P037" (solid, remove dead copper, pour order 37): 18.965,14.756 18.965,13.408 29.903,13.479 31.12,14.706 39.982,14.706 42.5,12.02 42.554,0.685 0.798,0.685 0.798,14.756
PGND on Top Layer "TOP_LAYER_PGND_P091" (solid, pour order 91): 41.976,12.485 41.976,5.476 42.237,5.216 62.973,5.216 62.967,5.223 62.967,9.451 45.01,9.451
NetC3_1 on Top Layer "TOP_LAYER_NETC3_1_P008" (solid, remove dead copper, pour order 8): 4.341,23.879 11.405,23.879 14.34,23.879 14.34,20.725 13.265,19.65 4.341,19.65
P5V0 on Top Layer "TOP_LAYER_P5V0_P049" (solid, remove dead copper, pour order 49): 21.319,22.067 21.319,19.175 19.339,17.196 19.339,13.599 30.153,13.599 30.153,16.211 24.07,16.211 22.019,18.977 22.019,22.067
PGND on Top Layer "TOP_LAYER_PGND_P040" (solid, remove dead copper, pour order 40): 0.744,14.561 14.892,14.561 19.038,14.561 19.038,17.39 18.175,17.39 17.393,17.39 17.397,18.607 14.297,18.607 13.733,18.042 11.46,18.042 11.46,19.302 4.341,19.42 4.341,24.258 0.744,24.258
BAT on Top Layer "TOP_LAYER_BAT_P002" (solid, remove dead copper, pour order 2): 36.563,7.09 33.244,7.09 33.244,5.707 36.327,5.707 36.986,4.985 36.986,0.627 78.786,0.627 78.786,4.985 41.737,4.985 41.262,5.46 38.283,5.46
SW2 on Top Layer "TOP_LAYER_SW2_P019" (solid, remove dead copper, pour order 19): 60.874,33.203 65.21,33.203 66.86,34.854 66.86,40.5 66.121,41.239 64.999,41.239 63.774,42.464 63.774,55.009 52.217,55.009 52.217,33.203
